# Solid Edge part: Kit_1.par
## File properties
Username: bmolnar
Dokumentum tartalom típus: 0
Author: bmolnar
Last saved by: bmolnar
Revision: 77
Sűrűség: 0,000 kg/m^3
Pontosság: 0,990
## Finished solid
Body 1: solid body, 33 faces, 39 edges, 35 vertices, 2 separate solids.
  Faces by surface: plane 11, cone 10, cylinder 8, torus 4
  Edges by curve: circle 31, line 8
Bounding box of the edges (mm; curved faces can reach further): 19.000 x 18.450 x 3.100, from (-9.5, -9.5, 48.6) to (9.5, 8.95, 51.7).
Cylindrical faces by radius (mm): R4.21 x1, R4.6 x1, R5.68 x1, R5.75 x1, R6.6 x1, R8.5 x1, R8.95 x1, R9.5 x1
Conical faces (half-angle, radius in mm at the cone's reference point): 3 deg R5.715 x1, 7 deg R5.2386 x1, 14 deg R4.105 x1, 14 deg R4.3042 x1, 17 deg R4.105 x1, 23 deg R4.6448 x1, 42.5 deg R4.0959 x1, 45 deg R4.75 x1, 45 deg R6.45 x1, 87 deg R4.0979 x1
Toroidal faces (ring radius, tube radius in mm): R4.5656 r0.1575 x1, R4.974 r0.2275 x1, R5.48 r0.2 x1, R7 r0.4 x1
Planar faces by outward normal: +z 4, -z 5, oblique 2
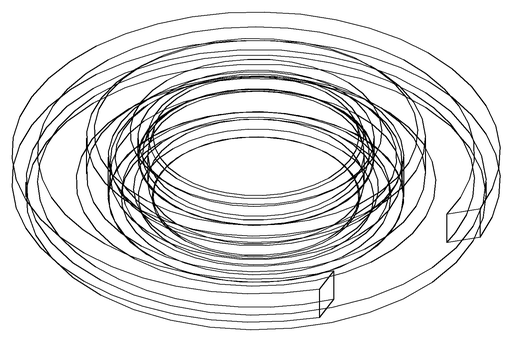
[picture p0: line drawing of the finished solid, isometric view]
